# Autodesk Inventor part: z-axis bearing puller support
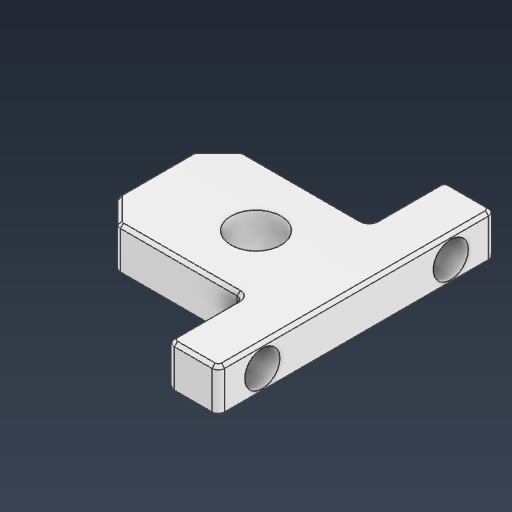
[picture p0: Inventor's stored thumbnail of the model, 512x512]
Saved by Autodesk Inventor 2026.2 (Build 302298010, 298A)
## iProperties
Created: 2026-04
Part Number: z-axis bearing puller support
Material: ABS 플라스틱
Document SubType Name: Modeling
Designer: work
Density: 1.06 g/cm^3
Appearance: 매끄러움 - 흰색
Mass: 0.652771 g
Surface Area: 7.03991 cm^2
Volume: 0.615822 cm^3
Author: work
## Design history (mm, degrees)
sketch "스케치1"
  geometry: L1 (0, 0)-(-8, 0); L2 (8, 5)-(-8, 5); L3 (-8, 5)-(-8, -5); L4 (-8, -5)-(8, -5); L5 (8, -5)-(8, 5); L6 (8, 5)-(-8, -5); L7 (-8, 5)-(8, -5); L8 (-8, 5)-(-4, 5); L9 (-4, 5)-(-4, 11); L10 (-4, 11)-(-8, 11); L11 (-8, 11)-(-8, 5); L12 (-8, -5)-(-4, -5); L13 (-4, -5)-(-4, -11); L14 (-4, -11)-(-8, -11); L15 (-8, -11)-(-8, -5); C1 r 2 at (0, 0); 3 further points
  constraints: 30 end point, 6 parallel, 4 horizontal, 3 perpendicular, 2 midpoint, 1 centre point, 1 coincident
  dimensions: "d0" = 4 diameter of C1; "d1" = 8 distance of L1.start L1.end; "d2" = 16 distance of L4.end L3.end; "d3" = 10 distance of L3.end L2.end; "d4" = 4 distance of L10.end L9.end; "d5" = 6 distance of L9.end L8.end; "d6" = 4 distance of L13.end L14.end; "d7" = 6 distance of L12.end L13.end
extrude "돌출1" new body sketch "스케치1" distance "d8" = 3.5; taper "d9" = 0 deg
sketch "스케치2"
  geometry: L1 (-5, 0)-(-5, 3.5); L2 (6, 3.5)-(-16, 3.5) reference; L3 (-12.5, 1.75)-(2.5, 1.75); C1 r 1.4 at (-12.5, 1.75); C2 r 1.4 at (2.5, 1.75); 1 further point
  constraints: 4 end point, 3 midpoint, 2 centre point, 2 coincident, 1 horizontal
  dimensions: "d10" = 15 distance of L3.start L3.end; "d11" = 2.8 diameter of C1; "d12" = 2.8 diameter of C2
extrude "돌출2" cut sketch "스케치2" extent not by distance; stored distance "d13" = 0; taper "d14" = 0 deg
chamfer "모따기1" distance "d15" = 2; stored, may be unused: second distance "d16" = 2, angle "d17" = 45 deg
fillet "모깎기1" dims "d18" = 0.5
chamfer "모따기2" distance "d19" = 0.25; stored, may be unused: second distance "d20" = 2, angle "d21" = 45 deg
node "솔리드1"
